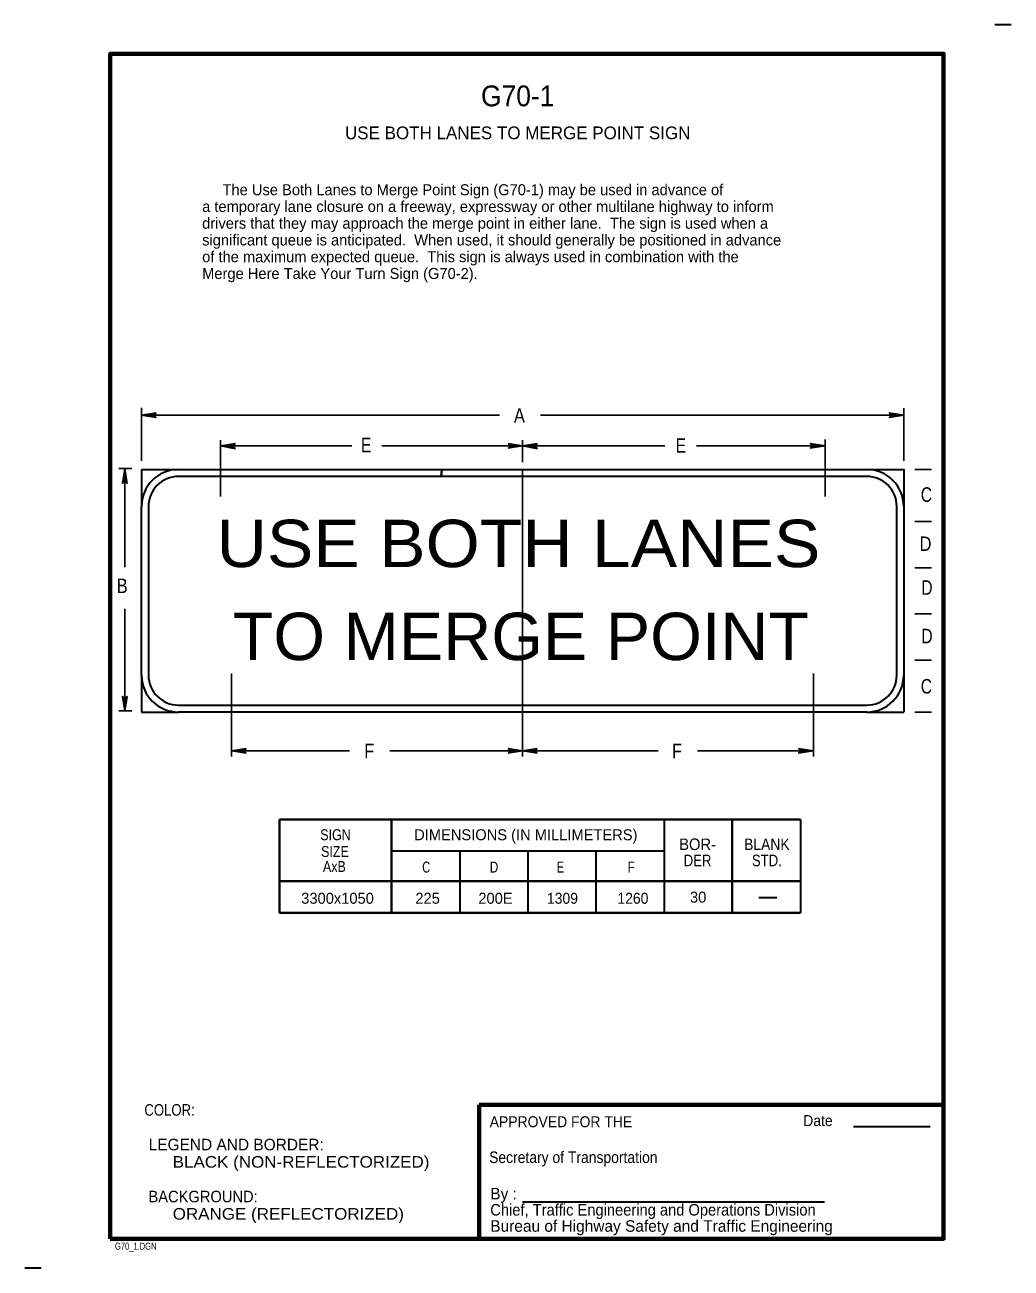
# Model space of a CAD drawing. Extents: x -2.572 to -2.359, y -78.725 to -78.456.
import ezdxf
from ezdxf.enums import TextEntityAlignment as Align

# ---------------------------------------------------------------- set-up
doc = ezdxf.new("R2010")
doc.units = 0
doc.header["$LTSCALE"] = 0.00095
doc.linetypes.add('DOT_DASHED', pattern=[7.7, 5, -1.2, 0.3, -1.2])
doc.layers.add('1', color=7, linetype='Continuous', lineweight=25)
doc.layers.add('3', color=7, linetype='Continuous', lineweight=35)

msp = doc.modelspace()

# ---------------------------------------------------------------- linework, layer by layer
at = {"layer": '1', "lineweight": 35}
for p, q in [((-2.358625, -78.456), (-2.362125, -78.456)), ((-2.546875, -78.55225), (-2.538875, -78.55225)), ((-2.546875, -78.55225), (-2.546875, -78.56025)), ((-2.538875, -78.55225), (-2.481875, -78.55225)), ((-2.546875, -78.59675), (-2.546875, -78.56025)), ((-2.545375, -78.56025), (-2.545375, -78.59675)), ((-2.383375, -78.59675), (-2.383375, -78.56025)), ((-2.381875, -78.56025), (-2.381875, -78.59675)), ((-2.546875, -78.59675), (-2.546875, -78.60475)), ((-2.381875, -78.59675), (-2.381875, -78.60475)), ((-2.538875, -78.60325), (-2.389875, -78.60325)), ((-2.546875, -78.60475), (-2.538875, -78.60475)), ((-2.389875, -78.60475), (-2.538875, -78.60475)), ((-2.389875, -78.60475), (-2.381875, -78.60475)), ((-2.39275, -78.6945), (-2.376125, -78.6945)), ((-2.464375, -78.71075), (-2.399, -78.71075)), ((-2.568625, -78.725125), (-2.572125, -78.725125))]:
    msp.add_line(p, q, dxfattribs=at)
at = {"layer": '1'}
for p, q in [((-2.546875, -78.550375), (-2.546875, -78.538875)), ((-2.546875, -78.5405), (-2.469375, -78.5405)), ((-2.4605, -78.5405), (-2.381875, -78.5405)), ((-2.381875, -78.550375), (-2.381875, -78.539)), ((-2.52975, -78.558125), (-2.52975, -78.545875)), ((-2.464375, -78.550625), (-2.464375, -78.545875)), ((-2.398875, -78.558125), (-2.398875, -78.54575)), ((-2.52975, -78.547125), (-2.501375, -78.547125)), ((-2.42675, -78.547125), (-2.398875, -78.547125)), ((-2.549, -78.552), (-2.55175, -78.552)), ((-2.5505, -78.573375), (-2.5505, -78.552)), ((-2.3795, -78.55225), (-2.375875, -78.55225)), ((-2.3795, -78.5635), (-2.375875, -78.5635)), ((-2.3795, -78.5735), (-2.375875, -78.5735)), ((-2.5505, -78.582375), (-2.5505, -78.6045)), ((-2.3795, -78.5835), (-2.375875, -78.5835)), ((-2.3795, -78.5935), (-2.375875, -78.5935)), ((-2.527375, -78.614375), (-2.527375, -78.596375)), ((-2.401375, -78.614375), (-2.401375, -78.596375)), ((-2.549, -78.6045), (-2.55175, -78.6045)), ((-2.3795, -78.60475), (-2.375875, -78.60475)), ((-2.464375, -78.608), (-2.464375, -78.614375)), ((-2.527375, -78.613125), (-2.501875, -78.613125)), ((-2.4265, -78.613125), (-2.401375, -78.613125))]:
    msp.add_line(p, q, dxfattribs=at)
at = {"layer": '1', "linetype": 'DOT_DASHED'}
msp.add_line((-2.464375, -78.608), (-2.464375, -78.55225), dxfattribs=at)
at = {"layer": '1', "lineweight": 70}
for q in [(-2.37325, -78.68975), (-2.47375, -78.71875)]:
    msp.add_line((-2.47375, -78.68975), q, dxfattribs=at)
msp.add_lwpolyline([(-2.553625, -78.71875), (-2.37325, -78.71875), (-2.37325, -78.46225), (-2.553625, -78.46225)], close=True, dxfattribs=at)
at = {"layer": '1'}
for points in [[(-2.543875, -78.540875), (-2.544, -78.54075), (-2.546875, -78.5405), (-2.543875, -78.540875), (-2.54375, -78.541), (-2.546875, -78.5405), (-2.544, -78.540375), (-2.543875, -78.54025), (-2.546875, -78.5405), (-2.54375, -78.54), (-2.543875, -78.54025)], [(-2.384875, -78.540125), (-2.38475, -78.540375), (-2.381875, -78.5405), (-2.384875, -78.540125), (-2.385, -78.54), (-2.381875, -78.5405), (-2.38475, -78.54075), (-2.384875, -78.540875), (-2.381875, -78.5405), (-2.385, -78.541), (-2.384875, -78.540875)], [(-2.52675, -78.5475), (-2.526875, -78.547375), (-2.52975, -78.547125), (-2.52675, -78.5475), (-2.526625, -78.54775), (-2.52975, -78.547125), (-2.526875, -78.547), (-2.52675, -78.546875), (-2.52975, -78.547125), (-2.526625, -78.546625), (-2.52675, -78.546875)], [(-2.467375, -78.54675), (-2.46725, -78.547), (-2.464375, -78.547125), (-2.467375, -78.54675), (-2.4675, -78.546625), (-2.464375, -78.547125), (-2.46725, -78.547375), (-2.467375, -78.5475), (-2.464375, -78.547125), (-2.4675, -78.547625), (-2.467375, -78.5475)], [(-2.461375, -78.5475), (-2.4615, -78.547375), (-2.464375, -78.547125), (-2.461375, -78.5475), (-2.46125, -78.54775), (-2.464375, -78.547125), (-2.4615, -78.547), (-2.461375, -78.546875), (-2.464375, -78.547125), (-2.46125, -78.546625), (-2.461375, -78.546875)], [(-2.401875, -78.54675), (-2.401875, -78.547), (-2.398875, -78.547125), (-2.401875, -78.54675), (-2.402125, -78.546625), (-2.398875, -78.547125), (-2.401875, -78.547375), (-2.401875, -78.5475), (-2.398875, -78.547125), (-2.402125, -78.547625), (-2.401875, -78.5475)], [(-2.494875, -78.547125), (-2.464375, -78.547125), (-2.433625, -78.547125)], [(-2.550875, -78.555), (-2.550625, -78.554875), (-2.5505, -78.552), (-2.550875, -78.555), (-2.551, -78.55525), (-2.5505, -78.552), (-2.550375, -78.554875), (-2.550125, -78.555), (-2.5505, -78.552), (-2.55, -78.55525), (-2.550125, -78.555)], [(-2.550125, -78.6015), (-2.550375, -78.601625), (-2.5505, -78.6045), (-2.550125, -78.6015), (-2.55, -78.601375), (-2.5505, -78.6045), (-2.550625, -78.601625), (-2.550875, -78.6015), (-2.5505, -78.6045), (-2.551, -78.601375), (-2.550875, -78.6015)], [(-2.524375, -78.6135), (-2.5245, -78.61325), (-2.527375, -78.613125), (-2.524375, -78.6135), (-2.52425, -78.613625), (-2.527375, -78.613125), (-2.5245, -78.613), (-2.524375, -78.61275), (-2.527375, -78.613125), (-2.52425, -78.612625), (-2.524375, -78.61275)], [(-2.493125, -78.613125), (-2.464375, -78.613125), (-2.435, -78.613125)], [(-2.467375, -78.61275), (-2.46725, -78.613), (-2.464375, -78.613125), (-2.467375, -78.61275), (-2.4675, -78.612625), (-2.464375, -78.613125), (-2.46725, -78.61325), (-2.467375, -78.6135), (-2.464375, -78.613125), (-2.4675, -78.613625), (-2.467375, -78.6135)], [(-2.461375, -78.6135), (-2.4615, -78.61325), (-2.464375, -78.613125), (-2.461375, -78.6135), (-2.46125, -78.613625), (-2.464375, -78.613125), (-2.4615, -78.613), (-2.461375, -78.61275), (-2.464375, -78.613125), (-2.46125, -78.612625), (-2.461375, -78.61275)], [(-2.404375, -78.61275), (-2.404375, -78.613), (-2.401375, -78.613125), (-2.404375, -78.61275), (-2.404625, -78.612625), (-2.401375, -78.613125), (-2.404375, -78.61325), (-2.404375, -78.6135), (-2.401375, -78.613125), (-2.404625, -78.613625), (-2.404375, -78.6135)]]:
    msp.add_lwpolyline(points, dxfattribs=at)
at = {"layer": '1', "lineweight": 35}
for points in [[(-2.481875, -78.55225), (-2.482, -78.55375), (-2.538875, -78.55375)], [(-2.389875, -78.55375), (-2.482, -78.55375), (-2.481875, -78.55225), (-2.389875, -78.55225)], [(-2.389875, -78.55225), (-2.381875, -78.55225), (-2.381875, -78.56025)]]:
    msp.add_lwpolyline(points, dxfattribs=at)
for centre, radius, start, end in [((-2.538875, -78.56025), 0.008, 90, 180), ((-2.538875, -78.56025), 0.0065, 90, 180), ((-2.389875, -78.56025), 0.008, 0, 90), ((-2.389875, -78.56025), 0.0065, 0, 90), ((-2.538875, -78.59675), 0.008, 180, 270), ((-2.538875, -78.59675), 0.0065, 180, 270), ((-2.389875, -78.59675), 0.0065, 270, 0), ((-2.389875, -78.59675), 0.008, 270, 0)]:
    msp.add_arc(centre, radius, start, end, dxfattribs=at)
at = {"layer": '3', "lineweight": 40}
for p, q in [((-2.517, -78.628), (-2.40425, -78.628)), ((-2.49275, -78.628), (-2.49275, -78.64825)), ((-2.419, -78.628), (-2.419, -78.64825)), ((-2.517, -78.641375), (-2.40425, -78.641375))]:
    msp.add_line(p, q, dxfattribs=at)
at = {"layer": '3'}
for p, q in [((-2.43375, -78.628), (-2.43375, -78.64825)), ((-2.40425, -78.628), (-2.40425, -78.64825)), ((-2.43375, -78.634875), (-2.49275, -78.634875)), ((-2.478, -78.634875), (-2.478, -78.64825)), ((-2.46325, -78.634875), (-2.46325, -78.64825)), ((-2.4485, -78.634875), (-2.4485, -78.64825)), ((-2.41325, -78.644875), (-2.409375, -78.644875))]:
    msp.add_line(p, q, dxfattribs=at)
at = {"layer": '3', "lineweight": 40}
msp.add_lwpolyline([(-2.517, -78.628), (-2.517, -78.64825), (-2.40425, -78.64825)], dxfattribs=at)

# ---------------------------------------------------------------- texts
at = {"layer": '1', "width": 0.95}
msp.add_text('G70-1', height=0.0045, dxfattribs=at).set_placement((-2.465438, -78.473625), align=Align.CENTER)
at = {"layer": '1'}
msp.add_text('USE BOTH LANES TO MERGE POINT SIGN', height=0.00275, dxfattribs=at).set_placement((-2.465438, -78.48075), align=Align.CENTER)
for s, height, p in [('     The Use Both Lanes to Merge Point Sign (G70-1) may be used in advance of', 0.002375, (-2.53375, -78.492875)), ('a temporary lane closure on a freeway, expressway or other multilane highway to inform', 0.002375, (-2.53375, -78.4965)), ('drivers that they may approach the merge point in either lane.  The sign is used when a', 0.002375, (-2.53375, -78.500125)), ('significant queue is anticipated.  When used, it should generally be positioned in advance', 0.002375, (-2.53375, -78.50375)), ('of the maximum expected queue.  This sign is always used in combination with the', 0.002375, (-2.53375, -78.507375)), ('Merge Here Take Your Turn Sign (G70-2).', 0.002375, (-2.53375, -78.511)), (' LEGEND AND BORDER:', 0.0025, (-2.54625, -78.699625)), ('By :', 0.0025, (-2.471375, -78.71025)), ('Bureau of Highway Safety and Traffic Engineering', 0.0025, (-2.471375, -78.71725))]:
    msp.add_text(s, height=height, dxfattribs=at).set_placement(p)
for s, height, width, p in [('A', 0.00315, 0.85, (-2.463875, -78.542125)), ('E', 0.003125, 0.8, (-2.497125, -78.5485)), ('E', 0.003125, 0.8, (-2.429, -78.548625)), ('C', 0.00315, 0.8, (-2.37575, -78.55925)), ('D', 0.003125, 0.85, (-2.375875, -78.569875)), ('B', 0.00315, 0.85, (-2.549875, -78.579)), ('D', 0.00315, 0.8, (-2.375625, -78.579375)), ('D', 0.00315, 0.8, (-2.375625, -78.589875)), ('C', 0.00315, 0.8, (-2.37575, -78.60075)), ('F', 0.003125, 0.85, (-2.4965, -78.61475)), ('F', 0.003125, 0.85, (-2.429875, -78.61475))]:
    msp.add_text(s, height=height, dxfattribs=dict(at, width=width)).set_placement(p, align=Align.RIGHT)
for s, height, width, p in [('USE BOTH LANES', 0.01025, 1.1, (-2.530625, -78.573375)), ('TO MERGE POINT', 0.01025, 1.05, (-2.527125, -78.5935)), ('COLOR:', 0.0025, 0.85, (-2.54625, -78.692125)), ('Date ', 0.002375, 0.95, (-2.403625, -78.694375)), ('APPROVED FOR THE', 0.002375, 0.95, (-2.4715, -78.694625)), ('Secretary of Transportation', 0.0025, 0.9, (-2.471625, -78.702375)), ('      BLACK (NON-REFLECTORIZED)', 0.0025, 1.1, (-2.54625, -78.703375)), (' BACKGROUND:', 0.0025, 0.95, (-2.54625, -78.710875)), ('      ORANGE (REFLECTORIZED)', 0.0025, 1.1, (-2.54625, -78.714625)), ('Chief, Traffic Engineering and Operations Division', 0.0025, 0.95, (-2.471375, -78.71375)), ('G70_1.DGN', 0.0015, 0.75, (-2.552625, -78.721125))]:
    msp.add_text(s, height=height, dxfattribs=dict(at, width=width)).set_placement(p)
at = {"layer": '3'}
for s, height, width, p in [('SIGN', 0.002375, 0.85, (-2.504875, -78.6325)), ('BOR-', 0.0025, 0.95, (-2.4265, -78.634625)), ('BLANK', 0.0025, 0.9, (-2.4115, -78.634625)), ('SIZE', 0.002375, 0.85, (-2.505, -78.636125)), ('DER', 0.0025, 0.85, (-2.4265, -78.638125)), ('STD.', 0.0025, 0.85, (-2.4115, -78.638125)), ('AxB', 0.002375, 0.85, (-2.505125, -78.639375)), ('C', 0.002375, 0.75, (-2.48525, -78.6395)), ('D', 0.002375, 0.8, (-2.470563, -78.6395)), ('E', 0.002375, 0.75, (-2.456187, -78.6395)), ('F', 0.002375, 0.8, (-2.440875, -78.6395)), ('1309', 0.002375, 0.95, (-2.45575, -78.64625)), ('1260', 0.002375, 0.95, (-2.4405, -78.64625))]:
    msp.add_text(s, height=height, dxfattribs=dict(at, width=width)).set_placement(p, align=Align.CENTER)
for s, p in [('DIMENSIONS (IN MILLIMETERS)', (-2.463687, -78.6325)), ('30', (-2.426375, -78.646)), ('3300x1050', (-2.504437, -78.64625)), ('225', (-2.484938, -78.64625)), ('200E', (-2.47025, -78.64625))]:
    msp.add_text(s, height=0.002375, dxfattribs=at).set_placement(p, align=Align.CENTER)

doc.saveas('drawing.dxf')
